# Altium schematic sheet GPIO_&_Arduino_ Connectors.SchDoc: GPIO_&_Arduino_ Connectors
size A3; CompanyName: STMicroelectronics; Organization: Microcontrollers Division; Address1: 12, Rue Jules HOROWITZ; Address2: 38019 Grenoble; Address3: FRANCE; DocumentNumber: MB1272; Revision: A-01; SheetNumber: 10; SheetTotal: 15; Project: STM32MP15-DISCO PI
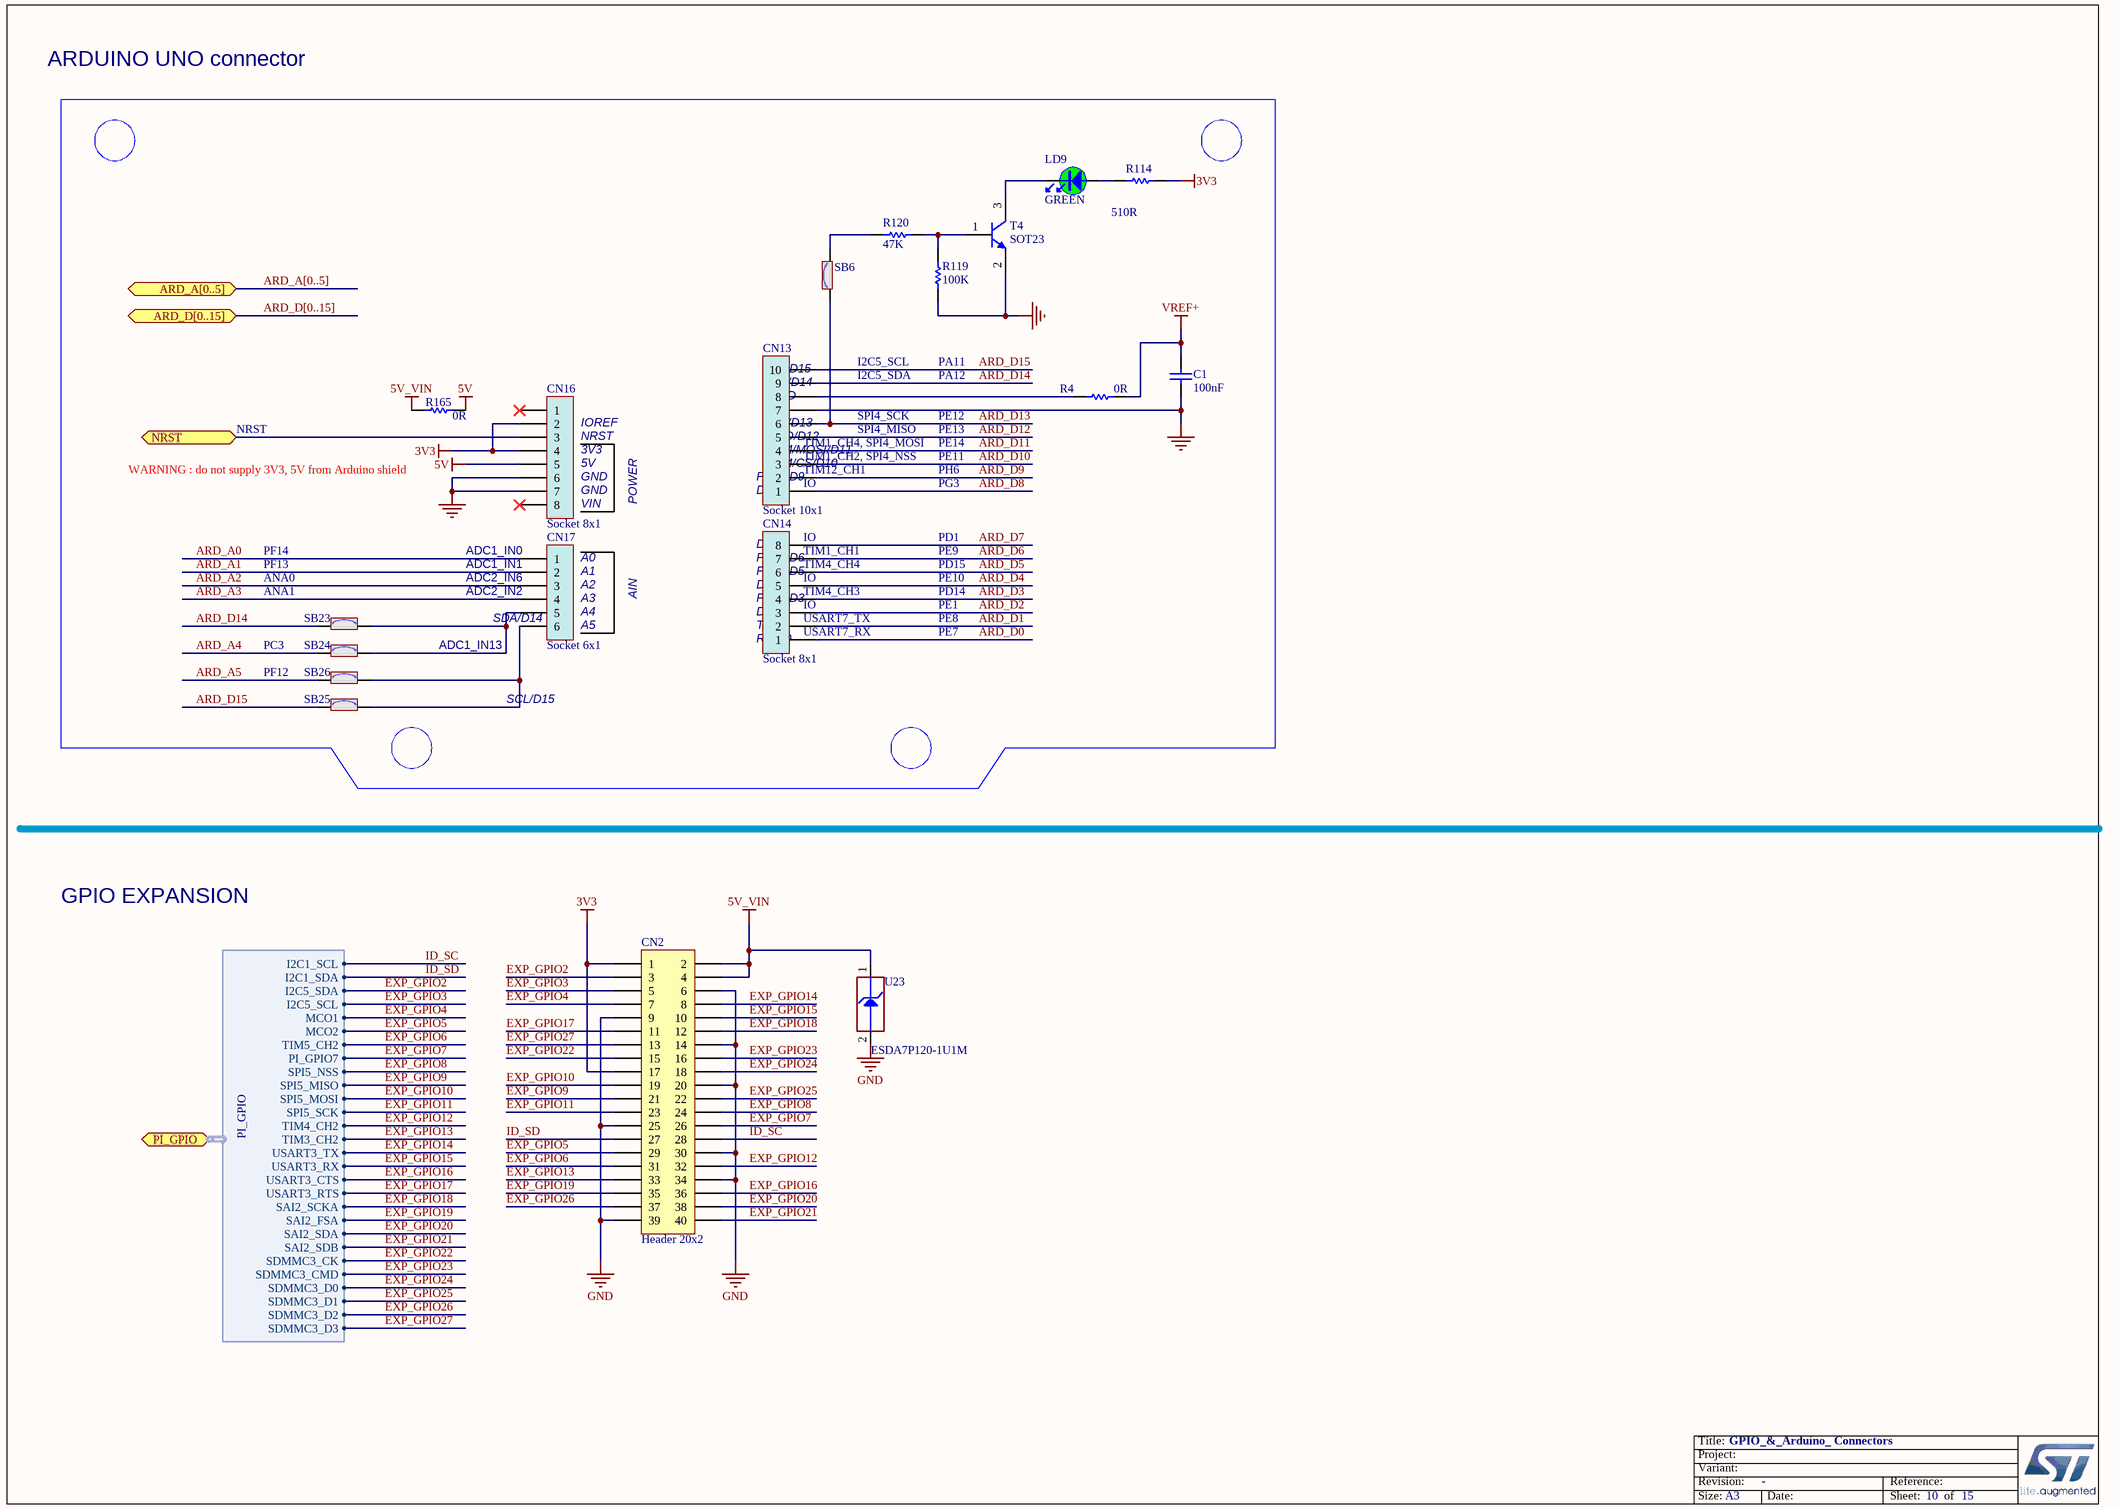
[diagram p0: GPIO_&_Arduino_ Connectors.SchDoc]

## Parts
C1  value 100nF  [C0402]
CN2  value Header 20x2  [CON_SAMTEC_TSW-120-07-G-D]
CN13  value Socket 10x1  [CON_SAMTEC_SSW-110-22-X-S-VS]
CN14  value Socket 8x1  [CON_SAMTEC_SSW-108-22-X-S-VS]
CN16  value Socket 8x1  [CON_SAMTEC_SSW-108-22-X-S-VS]
CN17  value Socket 6x1  [CON_SAMTEC_SSW-106-22-X-S-VS]
LD9  value GREEN  [LED_0603_GREEN]
R4  value 0R  [R0402]
R114  value 510R  [R0402]
R119  value 100K  [R0402]
R120  value 47K  [R0402]
R165  value 0R  [R0402]
SB6  (no value)  [SOLDER-BRIDGE_R0603-0R]
SB23  SB_ON  [SOLDER-BRIDGE_R0603-0R]  (value not drawn)
SB24  (no value)  [SOLDER-BRIDGE_R0603-0R]
SB25  SB_ON  [SOLDER-BRIDGE_R0603-0R]  (value not drawn)
SB26  (no value)  [SOLDER-BRIDGE_R0603-0R]
T4  value SOT23  [NPN_SOT23]
U23  value ESDA7P120-1U1M  [ESD_QFN1610_2N_1K_2A]  (hidden comment: ​Footprint needed DFN105P160X60-2N)

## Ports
ARD_A[0..5], ARD_D[0..15], NRST (bidir), PI_GPIO (harness PI_GPIO)

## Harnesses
PI_GPIO: I2C1_SCL, I2C1_SDA, I2C5_SDA, MCO1, MCO2, TIM5_CH2, PI_GPIO7, SPI5_NSS, SPI5_MISO, SPI5_MOSI, SPI5_SCK, TIM4_CH2, TIM3_CH2, USART3_TX, USART3_RX, USART3_CTS, USART3_RTS, SDMMC3_CK, SDMMC3_CMD, SDMMC3_D0, SDMMC3_D1, SDMMC3_D2, SDMMC3_D3, I2C5_SCL, SAI2_SCKA, SAI2_FSA, SAI2_SDA, SAI2_SDB

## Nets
3V3: CN2.1 CN2.17 CN16.2 CN16.4 R114.2
5V: CN16.5 R165.2
5V_VIN: CN2.2 CN2.4 R165.1 U23.1(IO1)
GND: C1.1 CN2.6 CN2.9 CN2.14 CN2.20 CN2.25 CN2.30 CN2.34 CN2.39 CN13.7 CN16.6 CN16.7 R119.1 T4.2(E) U23.2(GND)
VREF+: C1.2 R4.2
ARD_A0: CN17.1
ARD_A1: CN17.2
ARD_A2: CN17.3
ARD_A3: CN17.4
ARD_A4: SB24.1
ARD_A5: SB26.1
ARD_D0: CN14.1
ARD_D1: CN14.2
ARD_D2: CN14.3
ARD_D3: CN14.4
ARD_D4: CN14.5
ARD_D5: CN14.6
ARD_D6: CN14.7
ARD_D7: CN14.8
ARD_D8: CN13.1
ARD_D9: CN13.2
ARD_D10: CN13.3
ARD_D11: CN13.4
ARD_D12: CN13.5
ARD_D13: CN13.6 SB6.1
ARD_D14: CN13.9 SB23.1
ARD_D15: CN13.10 SB25.1
EXP_GPIO2: CN2.3 ; port PI_GPIO.I2C5_SDA
EXP_GPIO3: CN2.5 ; port PI_GPIO.I2C5_SCL
EXP_GPIO4: CN2.7 ; port PI_GPIO.MCO1
EXP_GPIO5: CN2.29 ; port PI_GPIO.MCO2
EXP_GPIO6: CN2.31 ; port PI_GPIO.TIM5_CH2
EXP_GPIO7: CN2.26 ; port PI_GPIO.PI_GPIO7
EXP_GPIO8: CN2.24 ; port PI_GPIO.SPI5_NSS
EXP_GPIO9: CN2.21 ; port PI_GPIO.SPI5_MISO
EXP_GPIO10: CN2.19 ; port PI_GPIO.SPI5_MOSI
EXP_GPIO11: CN2.23 ; port PI_GPIO.SPI5_SCK
EXP_GPIO12: CN2.32 ; port PI_GPIO.TIM4_CH2
EXP_GPIO13: CN2.33 ; port PI_GPIO.TIM3_CH2
EXP_GPIO14: CN2.8 ; port PI_GPIO.USART3_TX
EXP_GPIO15: CN2.10 ; port PI_GPIO.USART3_RX
EXP_GPIO16: CN2.36 ; port PI_GPIO.USART3_CTS
EXP_GPIO17: CN2.11 ; port PI_GPIO.USART3_RTS
EXP_GPIO18: CN2.12 ; port PI_GPIO.SAI2_SCKA
EXP_GPIO19: CN2.35 ; port PI_GPIO.SAI2_FSA
EXP_GPIO20: CN2.38 ; port PI_GPIO.SAI2_SDA
EXP_GPIO21: CN2.40 ; port PI_GPIO.SAI2_SDB
EXP_GPIO22: CN2.15 ; port PI_GPIO.SDMMC3_CK
EXP_GPIO23: CN2.16 ; port PI_GPIO.SDMMC3_CMD
EXP_GPIO24: CN2.18 ; port PI_GPIO.SDMMC3_D0
EXP_GPIO25: CN2.22 ; port PI_GPIO.SDMMC3_D1
EXP_GPIO26: CN2.37 ; port PI_GPIO.SDMMC3_D2
EXP_GPIO27: CN2.13 ; port PI_GPIO.SDMMC3_D3
ID_SC: CN2.28 ; port PI_GPIO.I2C1_SCL
ID_SD: CN2.27 ; port PI_GPIO.I2C1_SDA
NRST: CN16.3 ; port NRST
NetCN13_8: CN13.8 R4.1
NetCN17_5: CN17.5 SB23.2 SB24.2
NetCN17_6: CN17.6 SB25.2 SB26.2
NetLD9_1: LD9.1 R114.1
NetLD9_2: LD9.2 T4.3(C)
NetR119_2: R119.2 R120.2 T4.1(B)
NetR120_1: R120.1 SB6.2

Not connected (* = marked no-connect by the designer): CN16 1* 8*

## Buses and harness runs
bus ARD_A[0..5] = port ARD_A[0..5]
bus ARD_D[0..15] = port ARD_D[0..15]

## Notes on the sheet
- ARDUINO UNO connector
- (near CN13) SCL/D15
- I2C5_SCL
- I2C5_SDA
- PA11
- PA12
- NRST
- (near CN16) IOREF
- (near CN16) NRST
- (near CN16) 3V3
- (near CN13) SDA/D14
- (near CN13) SCK/D13
- (near CN13) MISO/D12
- (near CN13) PWM/MOSI/D11
- (near CN13) AVDD
- (near CN13) GND
- (near CN13) TIM1_CH4, SPI4_MOSI
- SPI4_SCK
- SPI4_MISO
- PE14
- PE13
- PE12
- WARNING : do not supply 3V3, 5V from Arduino shield
- (near CN16) 5V
- (near CN16) GND
- (near CN16) VIN
- POWER
- (near CN13) D8
- (near CN13) PWM/D9
- (near CN13) PWM/CS/D10
- (near CN13) TIM12_CH1
- (near CN13) TIM1_CH2, SPI4_NSS
- (near CN13) IO
- PG3
- PH6
- PE11
- ANA0
- PF14
- PF13
- (near CN17) ADC2_IN6
- (near CN17) ADC1_IN1
- ADC1_IN0
- (near CN17) A0
- (near CN17) A1
- (near CN17) A2
- (near CN14) D4
- (near CN14) PWM/D5
- (near CN14) PWM/D6
- (near CN14) D7
- (near CN14) TIM4_CH4
- (near CN14) TIM1_CH1
- (near CN14) IO
- PE10
- PD15
- PE9
- PD1
- ANA1
- PC3
- ADC1_IN13
- (near CN17) ADC2_IN2
- SDA/D14
- (near CN17) A3
- (near CN17) A4
- (near CN17) A5
- AIN
- (near CN14) RX/D0
- (near CN14) TX/D1
- (near CN14) D2
- (near CN14) PWM/D3
- (near CN14) USART7_RX
- (near CN14) USART7_TX
- (near CN14) TIM4_CH3
- PE7
- PE8
- PE1
- PD14
- PF12
- SCL/D15
- GPIO EXPANSION

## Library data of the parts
C1 = MCD-00006: Capacitor,100nF,16V,X7R,10%,0402; Manufacturer_Part_Number: CC0402KRX7R7BB104; Manufacturer: YAGEO; Alternate_Manufacturer: MURATA; Alternate_Manufacturer_Part_Number: GCM155R71C104KA55D; Provided_By: SUBCO; Initial_Board_Reference: mb1274
CN2 = MCD-00302: Header, 20x2, 2.54mm, VR, TH, Height 5.84mm/2.54mm; Manufacturer_Part_Number: TSW-120-07-G-D; Manufacturer: SAMTEC; Part_Type: Connector; Provided_By: SUBCO; Initial_Board_Reference: mb1272
CN13 = MCD-00301: Socket, 10x1, 2.54mm, VR, SMT, Height 9.78mm; Part_Type: Connector; Manufacturer_Part_Number: SSW-110-22-L-S-VS; Manufacturer: SAMTEC; Provided_By: SUBCO; Initial_Board_Reference: mb1272
CN14 CN16 = MCD-00300: Socket, 8x1, 2.54mm, VR, SMT, Height 9.78mm; Manufacturer_Part_Number: SSW-108-22-L-S-VS; Manufacturer: SAMTEC; Part_Type: Connector; Provided_By: SUBCO; Initial_Board_Reference: mb1272
CN17 = MCD-00299: Socket, 6x1, 2.54mm, VR, SMT, Height 9.78mm; Manufacturer_Part_Number: SSW-106-22-L-S-VS; Manufacturer: SAMTEC; Part_Type: Connector; Provided_By: SUBCO; Initial_Board_Reference: mb1272
LD9 = MCD-00050: LED, Green, 0603; Manufacturer_Part_Number: 19-213SYGC/S530-E2/TR8; Manufacturer: EVERLIGHT; Part_Type: Display; ECCN_US: EAR99; ECCN_EU: NEC; Provided_By: SUBCO; Initial_Board_Reference: mb1274
R4 R165 = MCD-00052: Resistor,0R,0402,5%,1/16W; Manufacturer_Part_Number: RC0402JR-070RL; Manufacturer: YAGEO; Provided_By: SUBCO; Initial_Board_Reference: mb1274
R114 = MCD-00064: Resistor,510R,0402,1%,1/16W; Manufacturer_Part_Number: RC0402FR-07510RL; Manufacturer: YAGEO; Provided_By: SUBCO; Initial_Board_Reference: mb1274
R119 = MCD-00059: Resistor,100K,0402,1%,1/16W; Manufacturer_Part_Number: RC0402FR-07100KL; Manufacturer: YAGEO; Alternate_Manufacturer_Part_Number: RT0402FRE07100KL; Provided_By: SUBCO; Initial_Board_Reference: mb1274
R120 = MCD-00063: Resistor,47K,0402,1%,1/16W; Manufacturer_Part_Number: RC0402FR-0747KL; Manufacturer: YAGEO; Provided_By: SUBCO; Initial_Board_Reference: mb1274
SB6 SB24 SB26 = MCD-00071: Solder Bridge ON; Part_Type: Mechanical; Manufacturer: YAGEO; Manufacturer_Part_Number: RC0603JR-070RL; Provided_By: SUBCO; Initial_Board_Reference: mb1274
SB23 SB25 = MCD-00071: Solder Bridge ON; Part_Type: Mechanical; Manufacturer: YAGEO; Manufacturer_Part_Number: RC0603JR-070RL; Provided_By: SUBCO; Initial_Board_Reference: MB1274
T4 = MCD-00073: NPN Bipolar Transistor; Manufacturer_Part_Number: BSR14; Manufacturer: ON SEMICONDUCTOR; Part_Type: IC; Alternate_Manufacturer_Part_Number: MMBT2222ALT1G / MMBT2222ALT3G; ECCN_US: EAR99; ECCN_EU: NEC; Provided_By: SUBCO; Initial_Board_Reference: mb1274
U23 = MCD-01026: High power transient voltage suppressor; Part_Type: Diode; Manufacturer: STMICROELECTRONICS; BMS_Part_Number: 9179046; ECCN_US: EAR99; ECCN_EU: NEC; Provided_By: SUBCO with ST control; Initial_Board_Reference: MB1378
